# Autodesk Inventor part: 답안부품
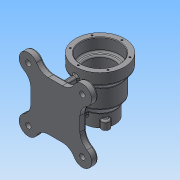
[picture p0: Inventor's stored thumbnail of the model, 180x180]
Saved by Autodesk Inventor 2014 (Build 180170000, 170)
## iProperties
Created: 2017-03
Part Number: 답안부품
Material: 일반
Document SubType Name: Modeling
Designer: NET
Density: 1 g/cm^3
Appearance: 기본값
Author: NET
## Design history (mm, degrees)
sketch "스케치2"
  geometry: L1 (0, 50)-(0, -35); L2 (27.5, -35)-(27.5, -27); L3 (27.5, -27)-(36, -15); L4 (36, -15)-(36, 19); L5 (36, 19)-(45, 30); L6 (45, 30)-(45, 50); L7 (45, 50)-(0, 50); L8 (27.5, -35)-(0, -35); 2 further points
  constraints: 16 end point, 3 parallel, 2 coincident, 2 perpendicular, 1 point on line, 1 vertical
  dimensions: "d6" = 90 diameter of L6.end L1; "d7" = 20 distance of L5.end L6.end; "d8" = 31 vertical distance of L4.end L6.end; "d9" = 65 vertical distance of L6.end L3.end; "d10" = 55 diameter of L2.end L1; "d14" = 72 diameter of L4 L1; "d20" = 85 distance of L1.end L1.start
revolve "회전1" sketch "스케치2" stored, may be unused: angle "d18" = 90 deg
sketch "스케치4"
  geometry: C1 r 27.5 at (0, 0) reference; C2 r 27.5 at (0, 0); C3 r 7 at (0, 27.5); C4 r 7 at (-23.816, -13.75); C5 r 7 at (23.816, -13.75)
  constraints: 4 centre point, 1 coincident, 1 vertical alignment, 7 other
  dimensions: "d21" = 55 diameter of C2; "d22" = 14 diameter of C3; "d23" = 27.5 distance of C1.centre C3.centre; "d26" = 360 deg dimension on C1.centre C3.centre (derived)
extrude "돌출1" join sketch "스케치4" distance "d28" = 15; taper "d29" = 0 deg
fillet "모깎기1" dims "d30" = 3
fillet "모깎기2" dims "d31" = 1
sketch "스케치5"
  geometry: L1 (-45, 50)-(45, 50) reference; L2 (45, 50)-(45, 30) reference; L3 (45, 30)-(36, 19) reference; L4 (36, 19)-(36, -15) reference; L5 (36, -15)-(27.5, -27) reference; L6 (27.5, -27)-(27.5, -34) reference; L7 (28.5, -35)-(31.5, -35) reference; L8 (34.5, -38)-(34.5, -50) reference; L9 (34.5, -50)-(-27.5, -50) reference; L10 (-27.5, -50)-(-27.5, -27) reference; L11 (-27.5, -27)-(-36, -15) reference; L12 (-36, -15)-(-36, 19) reference; L13 (-36, 19)-(-45, 30) reference; L14 (-45, 30)-(-45, 50) reference; L15 (0, 50)-(0, -50); L16 (0, -50)-(17.5, -50); L17 (17.5, -50)-(17.5, -23); L18 (20.5, -20)-(23, -20); L19 (26, -17)-(26, 24); L20 (29, 27)-(32, 27); L21 (35, 30)-(35, 50); L22 (0, 50)-(35, 50); A1 r 1 centre (28.5, -34) between (27.5, -34) and (28.5, -35) reference; A2 r 3 centre (31.5, -38) between (34.5, -38) and (31.5, -35) reference; A3 r 3 centre (32, 30) between (32, 27) and (35, 30); A4 r 3 centre (29, 24) between (29, 27) and (26, 24); A5 r 3 centre (23, -17) between (23, -20) and (26, -17); A6 r 3 centre (20.5, -23) between (20.5, -20) and (17.5, -23); 2 further points
  constraints: 16 end point, 8 point on circle, 8 tangent, 5 point on line, 4 centre point, 4 perpendicular, 2 equal radius, 2 parallel, 1 collinear, 1 midpoint
  dimensions: "d32" = 30 distance of L16.end point (17.5, -20); "d33" = 35 diameter of L17 L15; "d35" = 52 diameter of L19 L15; "d36" = 70 diameter of L21 L15; "d37" = 3 radius of A3; "d38" = 3 radius of A5; "d39" = 47 vertical distance of L20.start L18.end
revolve "회전2" sketch "스케치5" stored, may be unused: angle "d40" = 90 deg
chamfer "모따기1" distance "d41" = 1; stored, may be unused: second distance "d42" = 2, angle "d43" = 45 deg
fillet "모깎기3" dims "d44" = 3
chamfer "모따기2" distance "d45" = 1; stored, may be unused: second distance "d46" = 2, angle "d47" = 45 deg
sketch "스케치6"
  geometry: A1 r 7 centre (0, 27.5) between (6.999, 27.373) and (-6.999, 27.373) reference; 1 further point
  constraints: 1 coincident
hole "구멍1" sketch "스케치6" at (0, 27.5) diameter "d48" = 3.242; stored, may be unused: countersink angle "d52" = 90 deg, drill point angle "d54" = 118 deg; dims "d49" = 9, "d50" = 4, "d51" = 2, "d53" = 11
sketch "스케치11"
  geometry: L1 (-17.5, -49)-(-18.5, -50) reference; L2 (-18.5, -50)-(-27.5, -50) reference; L3 (-27.5, -50)-(-27.5, -27.955) reference; L4 (-28.052, -26.221)-(-35.448, -15.779) reference; L5 (-36, -14.045)-(-36, 17.929) reference; L6 (-36.678, 19.829)-(-44.322, 29.171) reference; L7 (-45, 31.071)-(-45, 50) reference; L8 (-45, 50)-(-36, 50) reference; L9 (-36, 50)-(-35, 49) reference; L10 (-35, 49)-(-35, 30) reference; L11 (-32, 27)-(-29, 27) reference; L12 (-26, 24)-(-26, -17) reference; L13 (-23, -20)-(-20.5, -20) reference; L14 (-17.5, -23)-(-17.5, -49) reference; L15 (34.5, -38)-(34.5, -50) reference; L16 (34.5, -50)-(29.121, -50) reference; L17 (29.121, -50)-(29.121, -39) reference; L18 (29.121, -39)-(27.5, -38.026) reference; L19 (27.5, -38.026)-(25.879, -39) reference; L20 (25.879, -39)-(25.879, -50) reference; L21 (25.879, -50)-(18.5, -50) reference; L22 (18.5, -50)-(17.5, -49) reference; L23 (17.5, -49)-(17.5, -23) reference; L24 (20.5, -20)-(23, -20) reference; L25 (26, -17)-(26, 24) reference; L26 (29, 27)-(32, 27) reference; L27 (35, 30)-(35, 49) reference; L28 (35, 49)-(36, 50) reference; L29 (36, 50)-(45, 50) reference; L30 (45, 50)-(45, 31.071) reference; L31 (44.322, 29.171)-(36.678, 19.829) reference; L32 (36, 17.929)-(36, -14.045) reference; L33 (35.448, -15.779)-(28.052, -26.221) reference; L34 (27.5, -27.955)-(27.5, -34) reference; L35 (28.5, -35)-(31.5, -35) reference; L36 (-36, 1.942)-(-70, 1.942); L37 (-70, 1.942)-(-70, -35.058); L38 (-70, -35.058)-(-27.5, -35.058); A1 r 3 centre (-30.5, -27.955) between (-27.5, -27.955) and (-28.052, -26.221) reference; A2 r 3 centre (-33, -14.045) between (-36, -14.045) and (-35.448, -15.779) reference; A3 r 3 centre (-39, 17.929) between (-36, 17.929) and (-36.678, 19.829) reference; A4 r 3 centre (-42, 31.071) between (-45, 31.071) and (-44.322, 29.171) reference; A5 r 3 centre (-32, 30) between (-35, 30) and (-32, 27) reference; A6 r 3 centre (-29, 24) between (-26, 24) and (-29, 27) reference; A7 r 3 centre (-23, -17) between (-26, -17) and (-23, -20) reference; A8 r 3 centre (-20.5, -23) between (-17.5, -23) and (-20.5, -20) reference; A9 r 3 centre (31.5, -38) between (34.5, -38) and (31.5, -35) reference; A10 r 3 centre (20.5, -23) between (20.5, -20) and (17.5, -23) reference; A11 r 3 centre (23, -17) between (23, -20) and (26, -17) reference; A12 r 3 centre (29, 24) between (29, 27) and (26, 24) reference; A13 r 3 centre (32, 30) between (32, 27) and (35, 30) reference; A14 r 3 centre (42, 31.071) between (44.322, 29.171) and (45, 31.071) reference; A15 r 3 centre (39, 17.929) between (36.678, 19.829) and (36, 17.929) reference; A16 r 3 centre (33, -14.045) between (35.448, -15.779) and (36, -14.045) reference; A17 r 3 centre (30.5, -27.955) between (28.052, -26.221) and (27.5, -27.955) reference; A18 r 1 centre (28.5, -34) between (27.5, -34) and (28.5, -35) reference; 1 further point
  constraints: 6 end point, 2 perpendicular, 1 midpoint, 1 parallel, 1 point on line
  dimensions: "d117" = 37 distance of L36.end L37.end; "d118" = 70 horizontal distance of L36.end point (0, 0)
feature "리브4" sketch "스케치11" dims "d101" = 1, "d102" = 8, "d103" = 0, "d104" = 0, "d105" = 1, "d106" = 1
node "작업 평면3"
sketch "스케치14"
  geometry: L1 (-45, 31.071)-(-45, 50) reference; L2 (-45, 50)-(-36, 50) reference; L3 (-36, 50)-(-35, 49) reference; L4 (-35, 49)-(-35, 30) reference; L5 (-32, 27)-(-29, 27) reference; L6 (-26, 24)-(-26, -17) reference; L7 (-23, -20)-(-20.5, -20) reference; L8 (-17.5, -23)-(-17.5, -49) reference; L9 (-17.5, -49)-(-18.5, -50) reference; L10 (-18.5, -50)-(-27.5, -50) reference; L11 (-27.5, -50)-(-27.5, -35.058) reference; L12 (-27.5, -35.058)-(-70, -35.058) reference; L13 (-70, -35.058)-(-70, 1.942) reference; L14 (-70, 1.942)-(-36, 1.942) reference; L15 (-36, 1.942)-(-36, 17.929) reference; L16 (-36.678, 19.829)-(-44.322, 29.171) reference; L17 (44.322, 29.171)-(36.678, 19.829) reference; L18 (36, 17.929)-(36, -14.045) reference; L19 (35.448, -15.779)-(28.052, -26.221) reference; L20 (27.5, -27.955)-(27.5, -34) reference; L21 (28.5, -35)-(31.5, -35) reference; L22 (34.5, -38)-(34.5, -50) reference; L23 (34.5, -50)-(29.121, -50) reference; L24 (29.121, -50)-(29.121, -39) reference; L25 (29.121, -39)-(27.5, -38.026) reference; L26 (27.5, -38.026)-(25.879, -39) reference; L27 (25.879, -39)-(25.879, -50) reference; L28 (25.879, -50)-(18.5, -50) reference; L29 (18.5, -50)-(17.5, -49) reference; L30 (17.5, -49)-(17.5, -23) reference; L31 (20.5, -20)-(23, -20) reference; L32 (26, -17)-(26, 24) reference; L33 (29, 27)-(32, 27) reference; L34 (35, 30)-(35, 49) reference; L35 (35, 49)-(36, 50) reference; L36 (36, 50)-(45, 50) reference; L37 (45, 50)-(45, 31.071) reference; L38 (-26, 0)-(-70, 0); L39 (-70, 0)-(-70, 37); L40 (-70, 37)-(-45, 37); A1 r 3 centre (-42, 31.071) between (-45, 31.071) and (-44.322, 29.171) reference; A2 r 3 centre (-32, 30) between (-35, 30) and (-32, 27) reference; A3 r 3 centre (-29, 24) between (-26, 24) and (-29, 27) reference; A4 r 3 centre (-23, -17) between (-26, -17) and (-23, -20) reference; A5 r 3 centre (-20.5, -23) between (-17.5, -23) and (-20.5, -20) reference; A6 r 3 centre (-39, 17.929) between (-36, 17.929) and (-36.678, 19.829) reference; A7 r 3 centre (42, 31.071) between (44.322, 29.171) and (45, 31.071) reference; A8 r 3 centre (39, 17.929) between (36.678, 19.829) and (36, 17.929) reference; A9 r 3 centre (33, -14.045) between (35.448, -15.779) and (36, -14.045) reference; A10 r 3 centre (30.5, -27.955) between (28.052, -26.221) and (27.5, -27.955) reference; A11 r 1 centre (28.5, -34) between (27.5, -34) and (28.5, -35) reference; A12 r 3 centre (31.5, -38) between (34.5, -38) and (31.5, -35) reference; A13 r 3 centre (20.5, -23) between (20.5, -20) and (17.5, -23) reference; A14 r 3 centre (23, -17) between (23, -20) and (26, -17) reference; A15 r 3 centre (29, 24) between (29, 27) and (26, 24) reference; A16 r 3 centre (32, 30) between (32, 27) and (35, 30) reference; 1 further point
  constraints: 6 end point, 4 point on line, 1 perpendicular
  dimensions: "d119" = 70 distance of point (0, 0) L38.end; "d120" = 37 distance of L38.end L39.end
feature "리브6" sketch "스케치14" dims "d121" = 1, "d122" = 8, "d123" = 0, "d124" = 0, "d125" = 1, "d126" = 1
node "작업 평면4"
sketch "스케치15"
  geometry: L1 (4, -70)-(-4, -70) reference; L2 (-4, -70)-(-4, -35.777) reference; L3 (4, -35.777)-(4, -70) reference; L4 (0, -70)-(25, -70); L5 (25, -70)-(18.14, -31.096); C1 r 26 at (0, 0) reference; A1 r 36 centre (0, 0) between (4, -35.777) and (-4, -35.777) reference; 1 further point
  constraints: 4 end point, 1 midpoint, 1 perpendicular, 1 point on circle
  dimensions: "d127" = 25 distance of L4.end L4.start; "d129" = 100 deg angle of L5 L4
feature "리브7" sketch "스케치15" dims "d131" = 1, "d132" = 8, "d133" = 0, "d134" = 0, "d135" = 1, "d136" = 1
sketch "스케치16"
  geometry: L1 (18.14, -31.096)-(25, -70) reference; L2 (25, -70)-(-4, -70) reference; L3 (-4, -70)-(-4, -35.777) reference; L4 (0, -70)-(-25, -70); L5 (-25, -70)-(-18.14, -31.096); C1 r 26 at (0, 0) reference; A1 r 36 centre (0, 0) between (18.14, -31.096) and (-4, -35.777) reference; 1 further point
  constraints: 4 end point, 1 point on circle, 1 point on line
  dimensions: "d137" = 25 distance of L4.start L4.end; "d138" = 100 deg angle of L4 L5
feature "리브8" sketch "스케치16" dims "d139" = 1, "d140" = 8, "d141" = 0, "d142" = 0, "d143" = 1, "d144" = 1
sketch "스케치17" dims "d147" = 140
  geometry: L1 (8, 0)-(0, 0) reference; L2 (29, 31.058)-(29, 39.058) reference; L3 (49, 80.058)-(-41, 80.058); L4 (-41, 80.058)-(-41, -9.942); L5 (-41, -9.942)-(49, -9.942); L6 (49, -9.942)-(49, 80.058); L7 (4, 35.058)-(53.497, -14.439); L8 (4, 35.058)-(4, -47.502); C1 r 17 at (53.497, -14.439); C2 r 17 at (53.497, 84.555); C3 r 17 at (-45.497, 84.555); C4 r 17 at (-45.497, -14.439); 5 further points
  constraints: 12 end point, 4 centre point, 4 midpoint, 3 parallel, 2 coincident, 1 horizontal, 1 horizontal alignment, 1 perpendicular, 1 vertical alignment, 12 other
  dimensions: "d145" = 90 distance of L5.end L3.start; "d146" = 90 distance of L4.end L5.end; "d148" = 45 deg angle of L8 L7; "d149" = 34 diameter of C1; "d152" = 360 deg dimension on L7.start C1.centre (derived)
extrude "돌출3" join sketch "스케치17" distance "d154" = 12; taper "d155" = 0 deg
fillet "모깎기10" dims "d156" = 3
fillet "모깎기11" dims "d157" = 3
fillet "모깎기12" dims "d158" = 25
fillet "모깎기13" dims "d159" = 3
sketch "스케치18"
  geometry: C1 r 5 at (-45.497, 14.439); C2 r 5 at (-45.497, -84.555); C3 r 5 at (53.497, -84.555); C4 r 5 at (53.497, 14.439); A1 r 14 centre (-45.497, 14.439) between (-33.279, 21.274) and (-52.332, 2.221) reference; A2 r 14 centre (-45.497, -84.555) between (-52.332, -72.337) and (-33.279, -91.39) reference; A3 r 14 centre (53.497, -84.555) between (41.279, -91.39) and (60.332, -72.337) reference; A4 r 14 centre (53.497, 14.439) between (60.332, 2.221) and (41.279, 21.274) reference; 1 further point
  constraints: 4 centre point, 4 coincident
  dimensions: "d160" = 10 diameter of C1; "d161" = 10 diameter of C2; "d162" = 10 diameter of C3; "d163" = 10 diameter of C4
extrude "돌출4" cut sketch "스케치18" stored distance "d164" = 10 (= d160); taper "d165" = 0 deg
sketch "스케치19" dims "d166" = 80
  geometry: C1 r 45 at (0, 0) reference; 2 further points
  constraints: 2 coincident, 2 vertical alignment, 2 other
hole "구멍2" sketch "스케치19" at (0, 40) diameter "d167" = 3.242; stored, may be unused: countersink angle "d171" = 90 deg, drill point angle "d173" = 118 deg; dims "d168" = 9, "d169" = 4, "d170" = 2, "d172" = 11
node "작업 평면5"
sketch "스케치20"
  geometry: C1 r 5 at (0, 0); 1 further point
  constraints: 1 centre point, 1 coincident
  dimensions: "d178" = 10 diameter of C1
extrude "돌출5" join sketch "스케치20" stored distance "d179" = 10 (= d160); taper "d180" = 0 deg
sketch "스케치21"
  geometry: C1 r 5 at (0, 0) reference; 1 further point
  constraints: 1 coincident
hole "구멍3" sketch "스케치21" at (0, 0) diameter "d181" = 4.134; stored, may be unused: countersink angle "d185" = 90 deg, drill point angle "d187" = 118 deg; dims "d182" = 9, "d183" = 4, "d184" = 2, "d186" = 64.25
fillet "모깎기14" dims "d188" = 3
sketch "스케치22"
  geometry: L1 (3, -75.058)-(5, -75.058) reference; L2 (46, -22.216)-(46, -47.9) reference; L3 (4, -35.058)-(4, -75.058); L4 (16.842, 9.942)-(-8.842, 9.942) reference; 1 further point
  constraints: 2 end point, 1 midpoint, 1 parallel, 1 other
  dimensions: "d190" = 37.94281 horizontal distance of point (41.943, -35.058) L3.end; "d192" = 45 distance from line of L4 point (41.943, -35.058)
feature "엠보싱1" sketch "스케치22" dims "d6" = 90, "d7" = 20, "d8" = 31, "d9" = 65, "d10" = 55, "d14" = 72, "d20" = 85, "d193" = 0.5, "d194" = 0
node "솔리드1"
pattern_circular "원형 패턴1" dims angle "d56" = 360 deg
pattern_circular "원형 패턴2" dims angle "d175" = 360 deg
node "절단 모서리 투영2"
node "절단 모서리 투영7"
node "절단 모서리 투영9"
node "절단 모서리 투영10"
node "절단 모서리 투영11"
